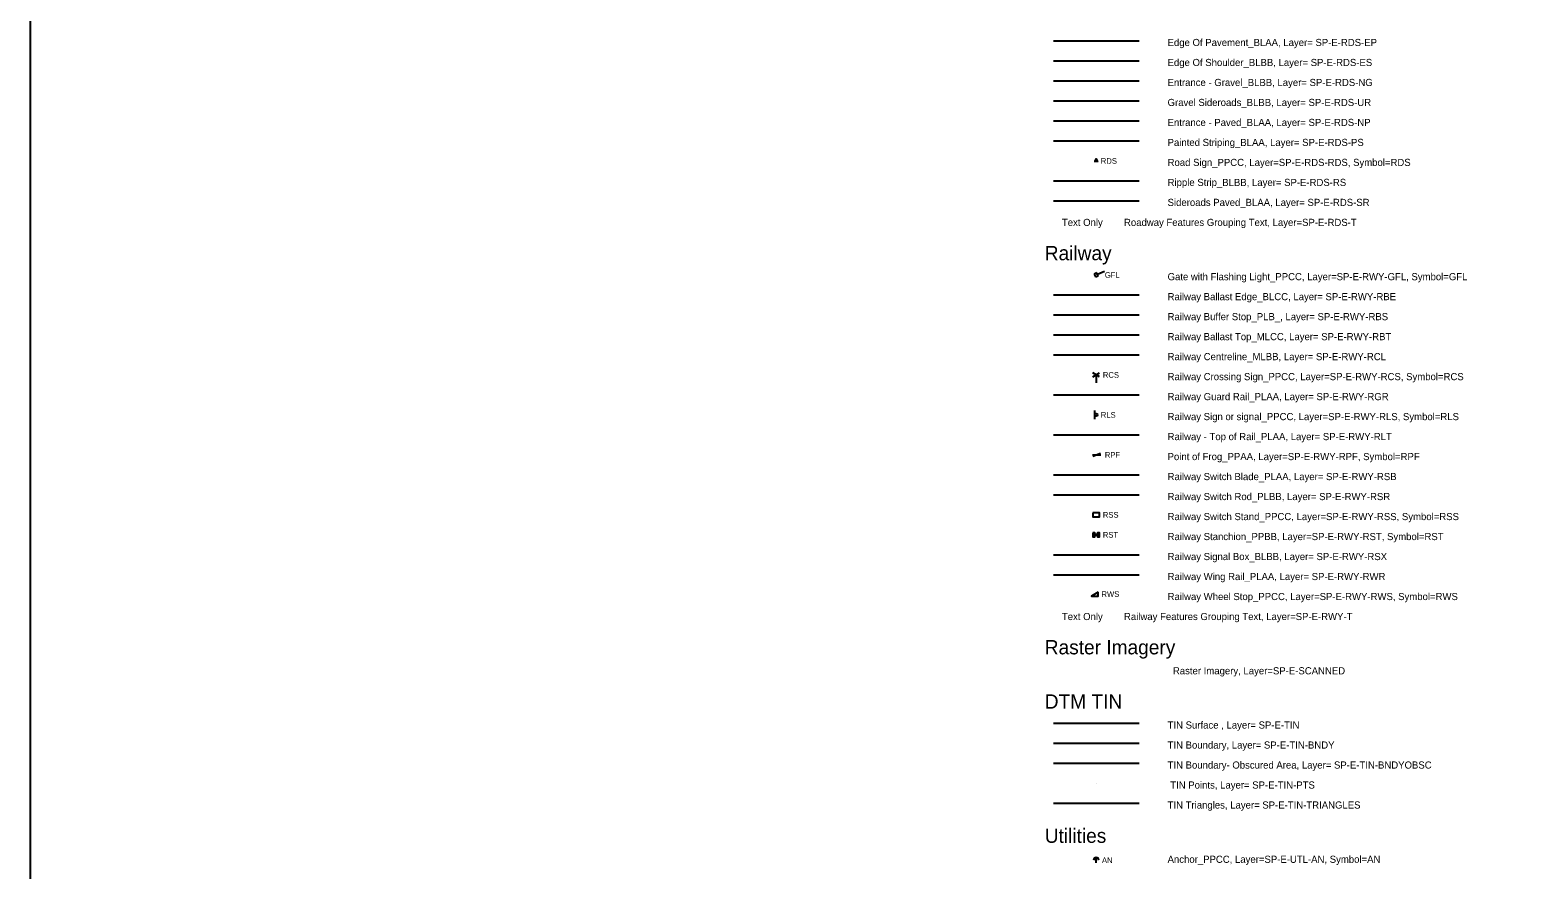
# Model space of a CAD drawing. Extents: x 500528 to 502626, y 4210261 to 4212624.
# Drawn here: x 500528 to 501056, y 4211145 to 4211439 of the extents above; entities that cross this region are included whole.
import ezdxf

# ---------------------------------------------------------------- set-up
doc = ezdxf.new("R2010")
doc.units = 0
for name, color, linetype in [('Default', 7, 'Continuous'), ('SP-E-RDS-EP', 7, 'Continuous'), ('SP-E-RDS-ES', 7, 'Continuous'), ('SP-E-RDS-NG', 7, 'Continuous'), ('SP-E-RDS-NP', 7, 'Continuous'), ('SP-E-RDS-PS', 7, 'Continuous'), ('SP-E-RDS-RDS', 7, 'Continuous'), ('SP-E-RDS-RS', 7, 'Continuous'), ('SP-E-RDS-SR', 7, 'Continuous'), ('SP-E-RDS-T', 7, 'Continuous'), ('SP-E-RDS-UR', 7, 'Continuous'), ('SP-E-RWY-GFL', 7, 'Continuous'), ('SP-E-RWY-RBE', 7, 'Continuous'), ('SP-E-RWY-RBS', 7, 'Continuous'), ('SP-E-RWY-RBT', 7, 'Continuous'), ('SP-E-RWY-RCL', 7, 'Continuous'), ('SP-E-RWY-RCS', 7, 'Continuous'), ('SP-E-RWY-RGR', 7, 'Continuous'), ('SP-E-RWY-RLS', 7, 'Continuous'), ('SP-E-RWY-RLT', 7, 'Continuous'), ('SP-E-RWY-RPF', 7, 'Continuous'), ('SP-E-RWY-RSB', 7, 'Continuous'), ('SP-E-RWY-RSR', 7, 'Continuous'), ('SP-E-RWY-RSS', 7, 'Continuous'), ('SP-E-RWY-RST', 7, 'Continuous'), ('SP-E-RWY-RSX', 7, 'Continuous'), ('SP-E-RWY-RWR', 7, 'Continuous'), ('SP-E-RWY-RWS', 7, 'Continuous'), ('SP-E-RWY-T', 7, 'Continuous'), ('SP-E-SCANNED', 7, 'Continuous'), ('SP-E-TIN', 7, 'Continuous'), ('SP-E-TIN-BNDY', 7, 'Continuous'), ('SP-E-TIN-BNDYOBSC', 7, 'Continuous'), ('SP-E-TIN-PTS', 7, 'Continuous'), ('SP-E-TIN-TRIANGLES', 7, 'Continuous'), ('SP-E-UTL-AN', 7, 'Continuous'), ('SP-E-UTL-T', 7, 'Continuous')]:
    doc.layers.add(name, color=color, linetype=linetype)

# ---------------------------------------------------------------- blocks, each defined once
blk = doc.blocks.new('RDS')
at = {"layer": 'SP-E-RDS-RDS'}
for points in [[(-0.041, -0.033), (0, 0.066), (0.041, -0.033)], [(0.075, -0.033), (-0.075, -0.033)]]:
    blk.add_lwpolyline(points, dxfattribs=at)
at = {"layer": 'SP-E-RDS-T'}
blk.add_text('RDS', height=0.2, dxfattribs=at).set_placement((0.162, -0.109))
blk = doc.blocks.new('GFL')
at = {"layer": 'SP-E-RWY-GFL'}
for points in [[(0.028, 0.072), (-0.072, 0.028)], [(0.028, 0.072), (-0.072, 0.028)], [(-0.072, 0.028), (-0.028, -0.072)], [(-0.072, 0.028), (-0.028, -0.072)], [(0, 0), (0, 0)], [(0.072, -0.028), (0.028, 0.072)], [(0.05, 0.022), (0.028, 0.072)], [(0.05, 0.022), (0.292, 0.128)], [(0.072, -0.028), (0.05, 0.022)], [(-0.028, -0.072), (0.072, -0.028)], [(-0.028, -0.072), (0.072, -0.028)]]:
    blk.add_lwpolyline(points, dxfattribs=at)
at = {"layer": 'SP-E-RWY-T'}
blk.add_text('GFL', height=0.2, dxfattribs=at).set_placement((0.303, -0.1))
blk = doc.blocks.new('RCS')
at = {"layer": 'SP-E-RWY-RCS'}
for points in [[(-0.121, -0.07), (0.121, 0.07)], [(0.121, -0.07), (-0.121, 0.07)], [(0, 0), (0, -0.28)], [(0, 0), (0, 0)]]:
    blk.add_lwpolyline(points, dxfattribs=at)
at = {"layer": 'SP-E-RWY-T'}
blk.add_text('RCS', height=0.2, dxfattribs=at).set_placement((0.233, -0.1))
blk = doc.blocks.new('RLS')
at = {"layer": 'SP-E-RWY-RLS'}
for points in [[(-0.05, -0.15), (-0.05, 0.15)], [(0, 0), (0, 0)]]:
    blk.add_lwpolyline(points, dxfattribs=at)
blk.add_circle((0, 0), 0.0495, dxfattribs=at)
at = {"layer": 'SP-E-RWY-T'}
blk.add_text('RLS', height=0.2, dxfattribs=at).set_placement((0.161, -0.1))
blk = doc.blocks.new('RPF')
at = {"layer": 'SP-E-RWY-RPF'}
blk.add_line((-0.125, 0), (0.161, 0), dxfattribs=at)
blk.add_lwpolyline([(-0.114, -0.05), (0.148, 0.065)], dxfattribs=at)
at = {"layer": 'SP-E-RWY-T'}
blk.add_text('RPF', height=0.2, dxfattribs=at).set_placement((0.303, -0.1))
blk = doc.blocks.new('RSS')
at = {"layer": 'SP-E-RWY-RSS'}
blk.add_lwpolyline([(-0.121, 0.07), (-0.121, -0.07), (0.121, -0.07), (0.121, 0.07), (-0.121, 0.07)], dxfattribs=at)
at = {"layer": 'SP-E-RWY-T'}
blk.add_text('RSS', height=0.2, dxfattribs=at).set_placement((0.233, -0.1))
blk = doc.blocks.new('RST')
at = {"layer": 'SP-E-RWY-RST'}
blk.add_lwpolyline([(-0.121, 0.07), (-0.121, -0.07), (-0.046, -0.07), (-0.046, -0.01), (0.046, -0.01), (0.046, -0.07), (0.121, -0.07), (0.121, 0.07), (0.046, 0.07), (0.046, 0.01), (-0.046, 0.01), (-0.046, 0.07), (-0.121, 0.07)], dxfattribs=at)
at = {"layer": 'SP-E-RWY-T'}
blk.add_text('RST', height=0.2, dxfattribs=at).set_placement((0.233, -0.1))
blk = doc.blocks.new('RWS')
at = {"layer": 'SP-E-RWY-RWS'}
blk.add_lwpolyline([(0.073, 0.094), (-0.169, -0.046), (0.073, -0.046), (0.073, 0.094)], dxfattribs=at)
at = {"layer": 'SP-E-RWY-T'}
blk.add_text('RWS', height=0.2, dxfattribs=at).set_placement((0.185, -0.076))
blk = doc.blocks.new('POINT_DISPLAY')
at = {"layer": 'Default'}
blk.add_line((0, 0), (0, 0), dxfattribs=at)
blk = doc.blocks.new('AN')
at = {"layer": 'SP-E-UTL-AN'}
blk.add_lwpolyline([(0, -0.19), (0, 0)], dxfattribs=at)
blk.add_arc((0, -0.09), 0.09, 360, 180, dxfattribs=at)
at = {"layer": 'SP-E-UTL-T'}
blk.add_text('AN', height=0.2, dxfattribs=at).set_placement((0.202, -0.195))

msp = doc.modelspace()

# ---------------------------------------------------------------- linework, layer by layer
at = {"layer": 'Default'}
msp.add_lwpolyline([(500528.35, 4212623.85), (500528.35, 4210260.5), (502626.48, 4210260.5), (502626.48, 4212623.85), (500528.35, 4212623.85)], dxfattribs=at)
msp.add_lwpolyline([(500528.35, 4210260.5), (502626.48, 4210260.5), (502626.48, 4212623.85), (500528.35, 4212623.85)], close=True, dxfattribs=at)
at = {"layer": 'SP-E-RDS-EP'}
msp.add_line((500886.55, 4211435.59), (500916.55, 4211435.59), dxfattribs=at)
at = {"layer": 'SP-E-RDS-ES'}
msp.add_line((500886.55, 4211428.59), (500916.55, 4211428.59), dxfattribs=at)
at = {"layer": 'SP-E-RDS-NG'}
msp.add_line((500886.55, 4211421.59), (500916.55, 4211421.59), dxfattribs=at)
at = {"layer": 'SP-E-RDS-NP'}
msp.add_line((500886.55, 4211407.59), (500916.55, 4211407.59), dxfattribs=at)
at = {"layer": 'SP-E-RDS-PS'}
msp.add_line((500886.55, 4211400.59), (500916.55, 4211400.59), dxfattribs=at)
at = {"layer": 'SP-E-RDS-RS'}
msp.add_line((500886.55, 4211386.59), (500916.55, 4211386.59), dxfattribs=at)
at = {"layer": 'SP-E-RDS-SR'}
msp.add_line((500886.55, 4211379.59), (500916.55, 4211379.59), dxfattribs=at)
at = {"layer": 'SP-E-RDS-UR'}
msp.add_line((500886.55, 4211414.59), (500916.55, 4211414.59), dxfattribs=at)
at = {"layer": 'SP-E-RWY-RBE'}
msp.add_line((500886.55, 4211346.59), (500916.55, 4211346.59), dxfattribs=at)
at = {"layer": 'SP-E-RWY-RBS'}
msp.add_line((500886.55, 4211339.59), (500916.55, 4211339.59), dxfattribs=at)
at = {"layer": 'SP-E-RWY-RBT'}
msp.add_line((500886.55, 4211332.59), (500916.55, 4211332.59), dxfattribs=at)
at = {"layer": 'SP-E-RWY-RCL'}
msp.add_line((500886.55, 4211325.59), (500916.55, 4211325.59), dxfattribs=at)
at = {"layer": 'SP-E-RWY-RGR'}
msp.add_line((500886.55, 4211311.59), (500916.55, 4211311.59), dxfattribs=at)
at = {"layer": 'SP-E-RWY-RLT'}
msp.add_line((500886.55, 4211297.59), (500916.55, 4211297.59), dxfattribs=at)
at = {"layer": 'SP-E-RWY-RSB'}
msp.add_line((500886.55, 4211283.59), (500916.55, 4211283.59), dxfattribs=at)
at = {"layer": 'SP-E-RWY-RSR'}
msp.add_line((500886.55, 4211276.59), (500916.55, 4211276.59), dxfattribs=at)
at = {"layer": 'SP-E-RWY-RSX'}
msp.add_line((500886.55, 4211255.59), (500916.55, 4211255.59), dxfattribs=at)
at = {"layer": 'SP-E-RWY-RWR'}
msp.add_line((500886.55, 4211248.59), (500916.55, 4211248.59), dxfattribs=at)
at = {"layer": 'SP-E-TIN'}
msp.add_line((500886.55, 4211196.59), (500916.55, 4211196.59), dxfattribs=at)
at = {"layer": 'SP-E-TIN-BNDY'}
msp.add_line((500886.55, 4211189.59), (500916.55, 4211189.59), dxfattribs=at)
at = {"layer": 'SP-E-TIN-BNDYOBSC'}
msp.add_line((500886.55, 4211182.59), (500916.55, 4211182.59), dxfattribs=at)
at = {"layer": 'SP-E-TIN-TRIANGLES'}
msp.add_line((500886.55, 4211168.59), (500916.55, 4211168.59), dxfattribs=at)

# ---------------------------------------------------------------- block references
at = {"layer": 'SP-E-RDS-RDS', "xscale": 10, "yscale": 10}
msp.add_blockref('RDS', (500901.55, 4211393.59), dxfattribs=at)
at = {"layer": 'SP-E-RWY-GFL', "xscale": 10, "yscale": 10}
msp.add_blockref('GFL', (500901.55, 4211353.59), dxfattribs=at)
at = {"layer": 'SP-E-RWY-RCS', "xscale": 10, "yscale": 10}
msp.add_blockref('RCS', (500901.55, 4211318.59), dxfattribs=at)
at = {"layer": 'SP-E-RWY-RLS', "xscale": 10, "yscale": 10}
msp.add_blockref('RLS', (500901.55, 4211304.59), dxfattribs=at)
at = {"layer": 'SP-E-RWY-RPF', "xscale": 10, "yscale": 10}
msp.add_blockref('RPF', (500901.55, 4211290.59), dxfattribs=at)
at = {"layer": 'SP-E-RWY-RSS', "xscale": 10, "yscale": 10}
msp.add_blockref('RSS', (500901.55, 4211269.59), dxfattribs=at)
at = {"layer": 'SP-E-RWY-RST', "xscale": 10, "yscale": 10}
msp.add_blockref('RST', (500901.55, 4211262.59), dxfattribs=at)
at = {"layer": 'SP-E-RWY-RWS', "xscale": 10, "yscale": 10}
msp.add_blockref('RWS', (500901.55, 4211241.59), dxfattribs=at)
at = {"layer": 'SP-E-TIN-PTS', "xscale": 10, "yscale": 10}
msp.add_blockref('POINT_DISPLAY', (500901.55, 4211175.59), dxfattribs=at)
at = {"layer": 'SP-E-UTL-AN', "xscale": 10, "yscale": 10}
msp.add_blockref('AN', (500901.55, 4211149.59), dxfattribs=at)

# ---------------------------------------------------------------- texts
at = {"layer": 'Default'}
for s, p in [('Railway ', (500883.55, 4211358.74)), ('Raster Imagery ', (500883.55, 4211220.74)), ('DTM TIN ', (500883.55, 4211201.74)), ('Utilities ', (500883.55, 4211154.74))]:
    msp.add_text(s, height=5, dxfattribs=at).set_placement(p)
at = {"layer": 'SP-E-RDS-EP'}
msp.add_text('Edge Of Pavement_BLAA, Layer= SP-E-RDS-EP ', height=2.5, dxfattribs=at).set_placement((500926.55, 4211433.74))
at = {"layer": 'SP-E-RDS-ES'}
msp.add_text('Edge Of Shoulder_BLBB, Layer= SP-E-RDS-ES ', height=2.5, dxfattribs=at).set_placement((500926.55, 4211426.74))
at = {"layer": 'SP-E-RDS-NG'}
msp.add_text('Entrance - Gravel_BLBB, Layer= SP-E-RDS-NG ', height=2.5, dxfattribs=at).set_placement((500926.55, 4211419.74))
at = {"layer": 'SP-E-RDS-NP'}
msp.add_text('Entrance - Paved_BLAA, Layer= SP-E-RDS-NP ', height=2.5, dxfattribs=at).set_placement((500926.55, 4211405.74))
at = {"layer": 'SP-E-RDS-PS'}
msp.add_text('Painted Striping_BLAA, Layer= SP-E-RDS-PS ', height=2.5, dxfattribs=at).set_placement((500926.55, 4211398.74))
at = {"layer": 'SP-E-RDS-RDS'}
msp.add_text('Road Sign_PPCC, Layer=SP-E-RDS-RDS, Symbol=RDS ', height=2.5, dxfattribs=at).set_placement((500926.55, 4211391.74))
at = {"layer": 'SP-E-RDS-RS'}
msp.add_text('Ripple Strip_BLBB, Layer= SP-E-RDS-RS ', height=2.5, dxfattribs=at).set_placement((500926.55, 4211384.74))
at = {"layer": 'SP-E-RDS-SR'}
msp.add_text('Sideroads Paved_BLAA, Layer= SP-E-RDS-SR ', height=2.5, dxfattribs=at).set_placement((500926.55, 4211377.74))
at = {"layer": 'SP-E-RDS-T'}
msp.add_text('Text Only        Roadway Features Grouping Text, Layer=SP-E-RDS-T', height=2.5, dxfattribs=at).set_placement((500889.55, 4211370.74))
at = {"layer": 'SP-E-RDS-UR'}
msp.add_text('Gravel Sideroads_BLBB, Layer= SP-E-RDS-UR ', height=2.5, dxfattribs=at).set_placement((500926.55, 4211412.74))
at = {"layer": 'SP-E-RWY-GFL'}
msp.add_text('Gate with Flashing Light_PPCC, Layer=SP-E-RWY-GFL, Symbol=GFL ', height=2.5, dxfattribs=at).set_placement((500926.55, 4211351.74))
at = {"layer": 'SP-E-RWY-RBE'}
msp.add_text('Railway Ballast Edge_BLCC, Layer= SP-E-RWY-RBE ', height=2.5, dxfattribs=at).set_placement((500926.55, 4211344.74))
at = {"layer": 'SP-E-RWY-RBS'}
msp.add_text('Railway Buffer Stop_PLB_, Layer= SP-E-RWY-RBS ', height=2.5, dxfattribs=at).set_placement((500926.55, 4211337.74))
at = {"layer": 'SP-E-RWY-RBT'}
msp.add_text('Railway Ballast Top_MLCC, Layer= SP-E-RWY-RBT ', height=2.5, dxfattribs=at).set_placement((500926.55, 4211330.74))
at = {"layer": 'SP-E-RWY-RCL'}
msp.add_text('Railway Centreline_MLBB, Layer= SP-E-RWY-RCL ', height=2.5, dxfattribs=at).set_placement((500926.55, 4211323.74))
at = {"layer": 'SP-E-RWY-RCS'}
msp.add_text('Railway Crossing Sign_PPCC, Layer=SP-E-RWY-RCS, Symbol=RCS ', height=2.5, dxfattribs=at).set_placement((500926.55, 4211316.74))
at = {"layer": 'SP-E-RWY-RGR'}
msp.add_text('Railway Guard Rail_PLAA, Layer= SP-E-RWY-RGR ', height=2.5, dxfattribs=at).set_placement((500926.55, 4211309.74))
at = {"layer": 'SP-E-RWY-RLS'}
msp.add_text('Railway Sign or signal_PPCC, Layer=SP-E-RWY-RLS, Symbol=RLS ', height=2.5, dxfattribs=at).set_placement((500926.55, 4211302.74))
at = {"layer": 'SP-E-RWY-RLT'}
msp.add_text('Railway - Top of Rail_PLAA, Layer= SP-E-RWY-RLT ', height=2.5, dxfattribs=at).set_placement((500926.55, 4211295.74))
at = {"layer": 'SP-E-RWY-RPF'}
msp.add_text('Point of Frog_PPAA, Layer=SP-E-RWY-RPF, Symbol=RPF ', height=2.5, dxfattribs=at).set_placement((500926.55, 4211288.74))
at = {"layer": 'SP-E-RWY-RSB'}
msp.add_text('Railway Switch Blade_PLAA, Layer= SP-E-RWY-RSB ', height=2.5, dxfattribs=at).set_placement((500926.55, 4211281.74))
at = {"layer": 'SP-E-RWY-RSR'}
msp.add_text('Railway Switch Rod_PLBB, Layer= SP-E-RWY-RSR ', height=2.5, dxfattribs=at).set_placement((500926.55, 4211274.74))
at = {"layer": 'SP-E-RWY-RSS'}
msp.add_text('Railway Switch Stand_PPCC, Layer=SP-E-RWY-RSS, Symbol=RSS ', height=2.5, dxfattribs=at).set_placement((500926.55, 4211267.74))
at = {"layer": 'SP-E-RWY-RST'}
msp.add_text('Railway Stanchion_PPBB, Layer=SP-E-RWY-RST, Symbol=RST ', height=2.5, dxfattribs=at).set_placement((500926.55, 4211260.74))
at = {"layer": 'SP-E-RWY-RSX'}
msp.add_text('Railway Signal Box_BLBB, Layer= SP-E-RWY-RSX ', height=2.5, dxfattribs=at).set_placement((500926.55, 4211253.74))
at = {"layer": 'SP-E-RWY-RWR'}
msp.add_text('Railway Wing Rail_PLAA, Layer= SP-E-RWY-RWR ', height=2.5, dxfattribs=at).set_placement((500926.55, 4211246.74))
at = {"layer": 'SP-E-RWY-RWS'}
msp.add_text('Railway Wheel Stop_PPCC, Layer=SP-E-RWY-RWS, Symbol=RWS ', height=2.5, dxfattribs=at).set_placement((500926.55, 4211239.74))
at = {"layer": 'SP-E-RWY-T'}
msp.add_text('Text Only        Railway Features Grouping Text, Layer=SP-E-RWY-T', height=2.5, dxfattribs=at).set_placement((500889.55, 4211232.74))
at = {"layer": 'SP-E-SCANNED'}
msp.add_text('  Raster Imagery, Layer=SP-E-SCANNED ', height=2.5, dxfattribs=at).set_placement((500926.55, 4211213.74))
at = {"layer": 'SP-E-TIN'}
msp.add_text('TIN Surface , Layer= SP-E-TIN ', height=2.5, dxfattribs=at).set_placement((500926.55, 4211194.74))
at = {"layer": 'SP-E-TIN-BNDY'}
msp.add_text('TIN Boundary, Layer= SP-E-TIN-BNDY ', height=2.5, dxfattribs=at).set_placement((500926.55, 4211187.74))
at = {"layer": 'SP-E-TIN-BNDYOBSC'}
msp.add_text('TIN Boundary- Obscured Area, Layer= SP-E-TIN-BNDYOBSC ', height=2.5, dxfattribs=at).set_placement((500926.55, 4211180.74))
at = {"layer": 'SP-E-TIN-PTS'}
msp.add_text(' TIN Points, Layer= SP-E-TIN-PTS ', height=2.5, dxfattribs=at).set_placement((500926.55, 4211173.74))
at = {"layer": 'SP-E-TIN-TRIANGLES'}
msp.add_text('TIN Triangles, Layer= SP-E-TIN-TRIANGLES ', height=2.5, dxfattribs=at).set_placement((500926.55, 4211166.74))
at = {"layer": 'SP-E-UTL-AN'}
msp.add_text('Anchor_PPCC, Layer=SP-E-UTL-AN, Symbol=AN ', height=2.5, dxfattribs=at).set_placement((500926.55, 4211147.74))

doc.saveas('drawing.dxf')
